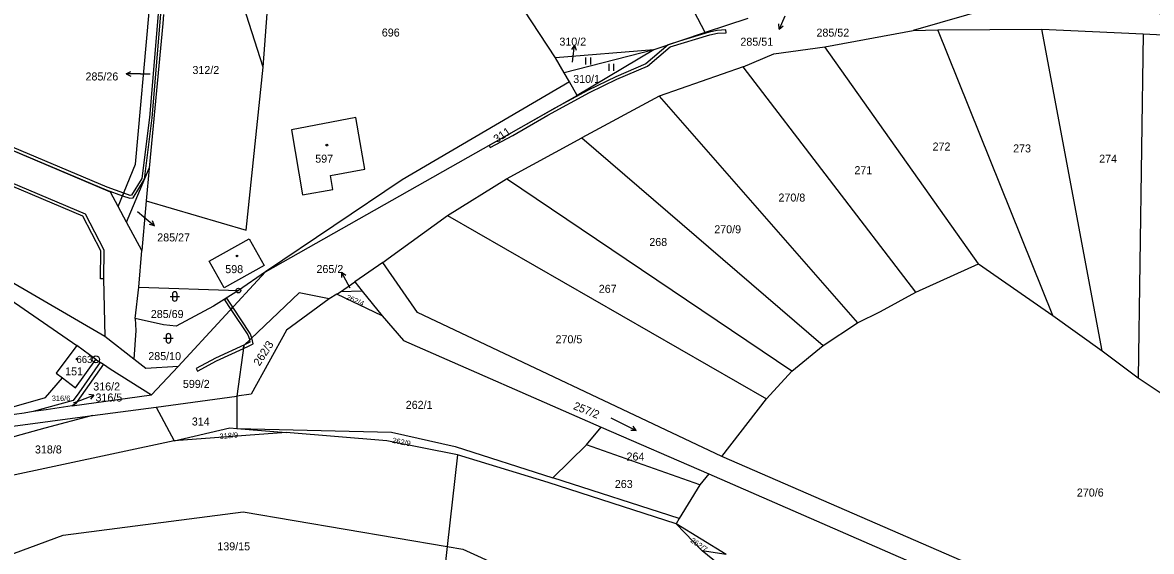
# Model space of a CAD drawing. Extents: x -758582 to -751794, y -998770 to -994350.
# Drawn here: x -755427.1 to -755187.4, y -995219.5 to -995107.1 of the extents above; entities that cross this region are included whole.
import ezdxf

# ---------------------------------------------------------------- set-up
doc = ezdxf.new("R2010")
doc.units = 0
for name, color, linetype in [('Hranice parcel', 7, 'Continuous'), ('Parcelní čísla', 7, 'Continuous'), ('Pop  PČ popisy', 7, 'Continuous'), ('Věcná břemena k části', 7, 'Continuous'), ('Značky bodu BP', 7, 'Continuous'), ('Značky budov', 7, 'Continuous'), ('Značky kultur', 7, 'Continuous')]:
    doc.layers.add(name, color=color, linetype=linetype)

msp = doc.modelspace()

# ---------------------------------------------------------------- linework, layer by layer
at = {"layer": 'Hranice parcel'}
for p, q in [((-755376, -995116.54), (-755385.42, -995087.06)), ((-755282.14, -995109.23), (-755292.32, -995089.69)), ((-755313.93, -995114.57), (-755323.21, -995100.33)), ((-755273.1, -995106.22), (-755282.14, -995109.23)), ((-755237.97, -995108.77), (-755232.73, -995108.66)), ((-755232.73, -995108.66), (-755210.61, -995108.52)), ((-755208.33, -995169.31), (-755232.73, -995108.66)), ((-755197.84, -995176.81), (-755210.61, -995108.52)), ((-755210.61, -995108.52), (-755189.11, -995109.48)), ((-755282.14, -995109.23), (-755293.05, -995112.87)), ((-755256.71, -995112.22), (-755237.97, -995108.77)), ((-755189.11, -995109.48), (-755190.21, -995182.55)), ((-755189.11, -995109.48), (-755168.07, -995110.52)), ((-755293.05, -995112.87), (-755313.93, -995114.57)), ((-755293.05, -995112.87), (-755312.07, -995117.77)), ((-755293.05, -995112.87), (-755309.28, -995122.58)), ((-755224.1, -995158.35), (-755256.71, -995112.22)), ((-755312.07, -995117.77), (-755313.93, -995114.57)), ((-755310.96, -995119.68), (-755312.07, -995117.77)), ((-755274.08, -995116.47), (-755291.91, -995122.72)), ((-755237.42, -995164.39), (-755274.08, -995116.47)), ((-755309.28, -995122.58), (-755310.96, -995119.68)), ((-755375.51, -995160.05), (-755309.28, -995122.58)), ((-755291.91, -995122.72), (-755308.34, -995131.56)), ((-755291.91, -995122.72), (-755249.77, -995170.88)), ((-755324.31, -995140.32), (-755308.34, -995131.56)), ((-755308.34, -995131.56), (-755257.08, -995175.73)), ((-755404.99, -995149.5), (-755400.19, -995138)), ((-755400.19, -995138), (-755400.81, -995144.96)), ((-755336.86, -995148.11), (-755324.31, -995140.32)), ((-755263.73, -995181.13), (-755324.31, -995140.32)), ((-755404.99, -995149.5), (-755406.77, -995146.2)), ((-755336.86, -995148.11), (-755269.12, -995187.02)), ((-755401.73, -995155.54), (-755404.99, -995149.5)), ((-755402.41, -995163.28), (-755401.73, -995155.54)), ((-755350.56, -995158.07), (-755356.53, -995162.19)), ((-755237.42, -995164.39), (-755224.1, -995158.35)), ((-755224.1, -995158.35), (-755208.33, -995169.31)), ((-755394.03, -995180.19), (-755375.51, -995160.05)), ((-755375.51, -995160.05), (-755381.26, -995164.02)), ((-755409.92, -995161.57), (-755409.63, -995173.78)), ((-755403.16, -995169.98), (-755402.41, -995163.28)), ((-755402.41, -995163.28), (-755381.26, -995164.02)), ((-755359.58, -995164.3), (-755356.53, -995162.19)), ((-755356.53, -995162.19), (-755354.93, -995164.18)), ((-755381.26, -995164.02), (-755386.55, -995167.37)), ((-755360.33, -995164.82), (-755361.97, -995165.77)), ((-755360.33, -995164.82), (-755359.58, -995164.3)), ((-755350.74, -995169.4), (-755360.33, -995164.82)), ((-755354.93, -995164.18), (-755359.58, -995164.3)), ((-755354.93, -995164.18), (-755350.74, -995169.4)), ((-755257.08, -995175.73), (-755249.77, -995170.88)), ((-755208.33, -995169.31), (-755197.84, -995176.81)), ((-755411.49, -995178.68), (-755415.57, -995175.73)), ((-755403.46, -995178.57), (-755409.63, -995173.78)), ((-755263.73, -995181.13), (-755257.08, -995175.73)), ((-755197.84, -995176.81), (-755190.21, -995182.55)), ((-755411.49, -995178.68), (-755410.59, -995179.26)), ((-755410.59, -995179.26), (-755409.92, -995179.7)), ((-755399.71, -995186.16), (-755394.03, -995180.19)), ((-755269.12, -995187.02), (-755263.73, -995181.13)), ((-755190.21, -995182.55), (-755182.08, -995187.92)), ((-755416.57, -995188.51), (-755399.71, -995186.16)), ((-755398.71, -995188.77), (-755381.59, -995186.49)), ((-755381.59, -995186.49), (-755381.6, -995193.33)), ((-755278.62, -995199.27), (-755269.12, -995187.02)), ((-755412.26, -995190.57), (-755398.71, -995188.77)), ((-755398.71, -995188.77), (-755394.86, -995195.98)), ((-755412.26, -995190.57), (-755422.34, -995193.29)), ((-755371.09, -995194.2), (-755394.86, -995195.98)), ((-755381.6, -995193.33), (-755371.09, -995194.2)), ((-755307.34, -995196.78), (-755304.23, -995193.02)), ((-755304.23, -995193.02), (-755281.37, -995202.97)), ((-755394.86, -995195.98), (-755431.62, -995203.8)), ((-755314.46, -995203.81), (-755307.34, -995196.78)), ((-755283.28, -995205.27), (-755307.34, -995196.78)), ((-755334.7, -995198.95), (-755336.91, -995218.43)), ((-755287.62, -995212.46), (-755314.46, -995203.81)), ((-755281.37, -995202.97), (-755283.28, -995205.27)), ((-755281.37, -995202.97), (-755238.36, -995221.7)), ((-755283.28, -995205.27), (-755287.62, -995212.46)), ((-755287.62, -995212.46), (-755288.3, -995213.59)), ((-755277.66, -995220.08), (-755288.3, -995213.59)), ((-755282.75, -995219.3), (-755288.3, -995213.59)), ((-755336.91, -995218.43), (-755338.81, -995235.22)), ((-755277.66, -995220.08), (-755282.75, -995219.3)), ((-755255.17, -995241.71), (-755282.75, -995219.3))]:
    msp.add_line(p, q, dxfattribs=at)
for points in [[(-755376, -995116.54), (-755373.96, -995088.98), (-755374.72, -995081.56)], [(-755169.07, -995108.29), (-755210.16, -995100.72), (-755237.97, -995108.77)], [(-755406.77, -995146.2), (-755403.11, -995137.2), (-755400.18, -995104.9)], [(-755397.16, -995105.39), (-755397.32, -995107.31), (-755400.19, -995138)], [(-755406.77, -995146.2), (-755408.44, -995143.1), (-755488.46, -995109.15)], [(-755274.08, -995116.47), (-755267.54, -995113.73), (-755256.71, -995112.22)], [(-755409.63, -995173.78), (-755430.61, -995161.51), (-755459.22, -995142.34), (-755487.3, -995127.73), (-755489.91, -995114.72)], [(-755409.92, -995161.57), (-755410.56, -995161.57), (-755410.47, -995155.58), (-755414.27, -995148.21), (-755488.32, -995116.88)], [(-755487.87, -995116.36), (-755413.78, -995147.7), (-755409.81, -995155.35), (-755409.92, -995161.57)], [(-755400.81, -995144.96), (-755379.61, -995151.17), (-755376, -995116.54)], [(-755310.96, -995119.68), (-755346.47, -995140.48), (-755375.51, -995160.05)], [(-755369.99, -995129.88), (-755367.61, -995143.67), (-755361.17, -995142.56), (-755361.69, -995139.6), (-755354.38, -995138.27), (-755355.38, -995132.54), (-755356.33, -995127.23), (-755369.99, -995129.88)], [(-755493.12, -995129.14), (-755461.12, -995144.5), (-755438.01, -995160.24), (-755415.57, -995175.73)], [(-755400.81, -995144.96), (-755400.97, -995146.56), (-755401.73, -995155.54)], [(-755350.56, -995158.07), (-755349.46, -995157.22), (-755336.86, -995148.11)], [(-755378.93, -995153.06), (-755375.79, -995158.71), (-755384.29, -995163.45), (-755387.43, -995157.81), (-755378.93, -995153.06)], [(-755278.62, -995199.27), (-755343.18, -995168.67), (-755350.56, -995158.07)], [(-755361.97, -995165.77), (-755368.35, -995164.52), (-755380.08, -995175.71), (-755381.59, -995186.49)], [(-755361.97, -995165.77), (-755371.06, -995172.44), (-755378.54, -995186.05), (-755381.59, -995186.49)], [(-755249.77, -995170.88), (-755244.92, -995168.48), (-755237.42, -995164.39)], [(-755386.55, -995167.37), (-755394.44, -995171.59), (-755397.18, -995171.34), (-755403.16, -995169.98)], [(-755403.16, -995169.98), (-755403.02, -995172.52), (-755403.46, -995178.57)], [(-755350.74, -995169.4), (-755346.19, -995174.64), (-755304.23, -995193.02)], [(-755415.57, -995175.73), (-755419.93, -995181.6), (-755418.6, -995182.6)], [(-755410.59, -995179.26), (-755415.15, -995185.73), (-755416.31, -995187.38), (-755424.8, -995189.75)], [(-755418.6, -995182.6), (-755415.82, -995184.7), (-755411.49, -995178.68)], [(-755409.92, -995179.7), (-755414.66, -995186.42), (-755415.82, -995188.07), (-755416.57, -995188.51)], [(-755409.92, -995179.7), (-755408.45, -995180.67), (-755399.71, -995186.16)], [(-755394.03, -995180.19), (-755400.89, -995180.56), (-755403.46, -995178.57)], [(-755441.05, -995192.13), (-755422.21, -995186.74), (-755418.6, -995182.6)], [(-755424.8, -995189.75), (-755426.77, -995190.05), (-755428.77, -995190.33), (-755441.05, -995192.13)], [(-755416.57, -995188.51), (-755422.04, -995189.35), (-755424.8, -995189.75)], [(-755447.53, -995198.48), (-755439.27, -995194.16), (-755412.26, -995190.57)], [(-755422.34, -995193.29), (-755434.38, -995196.59), (-755440.4, -995198.33)], [(-755394.86, -995195.98), (-755383.04, -995193.2), (-755381.6, -995193.33)], [(-755381.6, -995193.33), (-755348.72, -995194.12), (-755335.18, -995197.13), (-755314.46, -995203.81)], [(-755334.7, -995198.95), (-755349.76, -995195.97), (-755371.09, -995194.2)], [(-755288.3, -995213.59), (-755315.45, -995204.79), (-755334.7, -995198.95)], [(-755116.14, -995223.73), (-755201.55, -995232.75), (-755278.62, -995199.27)], [(-755481.13, -995251.3), (-755457.2, -995230.32), (-755418.43, -995216.03), (-755380.2, -995211.02), (-755336.91, -995218.43)], [(-755336.91, -995218.43), (-755333.62, -995218.99), (-755289.88, -995238.9), (-755260.53, -995258.59)]]:
    msp.add_lwpolyline(points, dxfattribs=at)
at = {"layer": 'Pop  PČ popisy'}
for p, q in [((-755265.21, -995105.74), (-755266.43, -995108.48)), ((-755266.43, -995108.48), (-755266.48, -995107.36)), ((-755266.43, -995108.48), (-755265.57, -995107.77)), ((-755309.86, -995111.88), (-755310.48, -995112.81)), ((-755310.23, -995114.86), (-755309.86, -995111.88)), ((-755309.86, -995111.88), (-755309.49, -995112.94)), ((-755310.31, -995115.48), (-755310.23, -995114.86)), ((-755405.07, -995117.97), (-755404.07, -995117.47)), ((-755402.07, -995117.97), (-755405.07, -995117.97)), ((-755405.07, -995117.97), (-755404.07, -995118.47)), ((-755402.07, -995117.97), (-755399.98, -995117.97)), ((-755402.64, -995147.25), (-755401.36, -995148.33)), ((-755401.36, -995148.33), (-755399.06, -995150.26)), ((-755399.06, -995150.26), (-755399.51, -995149.23)), ((-755399.06, -995150.26), (-755400.15, -995150)), ((-755357.91, -995162.76), (-755359.36, -995160.14)), ((-755359.36, -995160.14), (-755358.44, -995160.77)), ((-755359.36, -995160.14), (-755359.32, -995161.25)), ((-755357.5, -995163.51), (-755357.91, -995162.76)), ((-755416.27, -995187.91), (-755414.73, -995187.32)), ((-755414.73, -995187.32), (-755411.93, -995186.24)), ((-755411.93, -995186.24), (-755413.04, -995186.14)), ((-755411.93, -995186.24), (-755412.68, -995187.07))]:
    msp.add_line(p, q, dxfattribs=at)
at = {"layer": 'Věcná břemena k části'}
for points in [[(-755395.8, -995080.39), (-755395.82, -995080.72), (-755395.7, -995081.09), (-755396.79, -995089.66), (-755397.36, -995094.13), (-755398.29, -995105.21), (-755400.13, -995127.25), (-755401.72, -995140.19), (-755403.95, -995143.76), (-755404.25, -995143.81), (-755405.6, -995143.32), (-755405.83, -995143.88), (-755404.31, -995144.43), (-755403.59, -995144.3), (-755401.18, -995140.38), (-755399.53, -995127.31), (-755397.69, -995105.3), (-755396.76, -995094.19), (-755396.32, -995090.7), (-755395.08, -995081.03), (-755395.09, -995080.61), (-755395.09, -995080.46)], [(-755491.6, -995108.07), (-755490.93, -995108.21), (-755490.42, -995108.27), (-755489.65, -995108.38), (-755489.18, -995108.44), (-755488.38, -995108.79), (-755460.96, -995120.57), (-755445.93, -995127.19), (-755409.35, -995142.61), (-755405.83, -995143.88), (-755405.6, -995143.32), (-755409.13, -995142.05), (-755445.69, -995126.63), (-755460.72, -995120.01), (-755488.25, -995108.19), (-755489.02, -995107.86), (-755489.57, -995107.78), (-755490.33, -995107.68), (-755490.83, -995107.61), (-755491.5, -995107.48), (-755493.05, -995107.17), (-755493.15, -995107.76)], [(-755328.03, -995133.19), (-755327.78, -995133.66), (-755322.98, -995131.05), (-755315.54, -995126.77), (-755306.69, -995121.96), (-755300.86, -995119.13), (-755294.4, -995116.38), (-755289.56, -995112.27), (-755281.12, -995109.73), (-755279.5, -995109.35), (-755277.7, -995109.25), (-755277.74, -995108.65), (-755279.58, -995108.75), (-755281.28, -995109.15), (-755287.57, -995111.04), (-755290, -995111.85), (-755294.72, -995115.86), (-755301.1, -995118.59), (-755306.97, -995121.42), (-755314.02, -995125.26)], [(-755383.71, -995165.63), (-755384.21, -995165.97), (-755382.84, -995168.03), (-755382.43, -995167.57)], [(-755382.43, -995167.57), (-755382.84, -995168.03), (-755379.26, -995173.44), (-755378.89, -995174.32), (-755378.86, -995174.54), (-755378.38, -995174.09), (-755378.72, -995173.16)], [(-755380.17, -995176.34), (-755380.08, -995175.71), (-755379.94, -995175.57), (-755386.13, -995178.4), (-755390.22, -995180.6), (-755389.94, -995181.12), (-755385.87, -995178.94)], [(-755378.79, -995175.01), (-755379.94, -995175.57), (-755380.08, -995175.71), (-755380.17, -995176.34), (-755379.1, -995175.85), (-755378.13, -995175.35), (-755378.38, -995174.09), (-755378.86, -995174.54)]]:
    msp.add_lwpolyline(points, close=True, dxfattribs=at)
at = {"layer": 'Značky bodu BP'}
for centre, radius in [((-755381.26, -995164.02), 0.5), ((-755381.26, -995164.02), 0.0303), ((-755411.52, -995178.65), 0.75), ((-755411.52, -995178.65), 0.03)]:
    msp.add_circle(centre, radius, dxfattribs=at)
at = {"layer": 'Značky budov'}
for centre in [(-755362.45, -995133.13), (-755381.54, -995156.68), (-755415.51, -995178.57)]:
    msp.add_circle(centre, 0.175, dxfattribs=at)
at = {"layer": 'Značky kultur'}
for p, q in [((-755307.44, -995116), (-755307.44, -995114.5)), ((-755306.44, -995116), (-755306.44, -995114.5)), ((-755302.52, -995117.35), (-755302.52, -995115.85)), ((-755301.52, -995117.35), (-755301.52, -995115.85)), ((-755395.77, -995165.27), (-755393.77, -995165.27)), ((-755395.27, -995164.77), (-755395.27, -995165.77)), ((-755394.27, -995165.77), (-755394.27, -995164.77)), ((-755397.12, -995174.17), (-755395.12, -995174.17)), ((-755396.62, -995173.67), (-755396.62, -995174.67)), ((-755395.62, -995174.67), (-755395.62, -995173.67)), ((-755302.19, -995191.1), (-755296.79, -995193.73)), ((-755296.79, -995193.73), (-755297.89, -995193.75)), ((-755296.79, -995193.73), (-755297.45, -995192.85))]:
    msp.add_line(p, q, dxfattribs=at)
for centre, start, end in [((-755394.77, -995164.77), 0, 180), ((-755394.77, -995165.77), 180, 359.9879), ((-755396.12, -995173.67), 0, 180), ((-755396.12, -995174.67), 180, 359.9879)]:
    msp.add_arc(centre, 0.5, start, end, dxfattribs=at)

# ---------------------------------------------------------------- texts
at = {"layer": 'Parcelní čísla'}
for s, height, p in [('696', 1.7, (-755350.79, -995110.06)), ('285/52', 1.7, (-755258.49, -995110.08)), ('310/2', 1.7, (-755313.08, -995111.99)), ('285/51', 1.7, (-755274.64, -995112.01)), ('285/26', 1.7, (-755413.71, -995119.39)), ('312/2', 1.7, (-755391.01, -995118.02)), ('310/1', 1.7, (-755310.15, -995119.92)), ('272', 1.7, (-755233.83, -995134.28)), ('273', 1.7, (-755216.73, -995134.68)), ('597', 1.7, (-755364.93, -995136.86)), ('274', 1.7, (-755198.45, -995136.86)), ('271', 1.7, (-755250.43, -995139.3)), ('270/8', 1.7, (-755266.56, -995145.12)), ('285/27', 1.7, (-755398.48, -995153.59)), ('270/9', 1.7, (-755280.19, -995151.86)), ('268', 1.7, (-755293.99, -995154.56)), ('598', 1.7, (-755384.03, -995160.33)), ('265/2', 1.7, (-755364.67, -995160.3)), ('267', 1.7, (-755304.72, -995164.51)), ('285/69', 1.7, (-755399.85, -995169.86)), ('270/5', 1.7, (-755313.9, -995175.23)), ('285/10', 1.7, (-755400.38, -995178.8)), ('151', 1.7, (-755418.04, -995182.04)), ('599/2', 1.7, (-755393.03, -995184.71)), ('316/2', 1.7, (-755412.07, -995185.26)), ('316/6', 1.14, (-755420.87, -995187.48)), ('316/5', 1.7, (-755411.59, -995187.6)), ('262/1', 1.7, (-755345.71, -995189.16)), ('314', 1.7, (-755391.14, -995192.7)), ('318/8', 1.7, (-755424.45, -995198.64)), ('264', 1.7, (-755298.82, -995200.14)), ('263', 1.7, (-755301.31, -995205.97)), ('270/6', 1.7, (-755203.19, -995207.79)), ('139/15', 1.7, (-755385.72, -995219.22))]:
    msp.add_text(s, height=height, dxfattribs=at).set_placement(p)
for s, height, rotation, p in [('311', 1.7, 34, (-755326.35, -995132.73)), ('262/4', 1.14, 337, (-755358.48, -995165.86)), ('262/3', 1.7, 57, (-755376.77, -995180.19)), ('257/2', 1.7, 338, (-755310.28, -995189.17)), ('318/9', 1.14, 5, (-755385.19, -995195.58)), ('262/9', 1.14, 349, (-755348.65, -995196.37)), ('262/7', 1.14, 325, (-755285.37, -995217.38))]:
    msp.add_text(s, height=height, rotation=rotation, dxfattribs=at).set_placement(p)
at = {"layer": 'Značky bodu BP'}
msp.add_text('663', height=1.5, dxfattribs=at).set_placement((-755415.62, -995179.4))

doc.saveas('drawing.dxf')
